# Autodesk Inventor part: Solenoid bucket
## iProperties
Created: 2008-10
Part Number: Solenoid bucket
Document SubType Name: Modeling
Designer: the-dude
Density: 1 g/cm^3
Author: the-dude
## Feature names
1. Cover outline [Extrusion]
2. Solenoid pocket [Extrusion]
3. Revolution3
4. Coil1
5. Rectangular Pattern2
6. Jaw screw holes [Extrusion]
7. Rough removal [Extrusion]
8. Stepped surfacing
9. Inclined surfacing
10. Extrusion15
